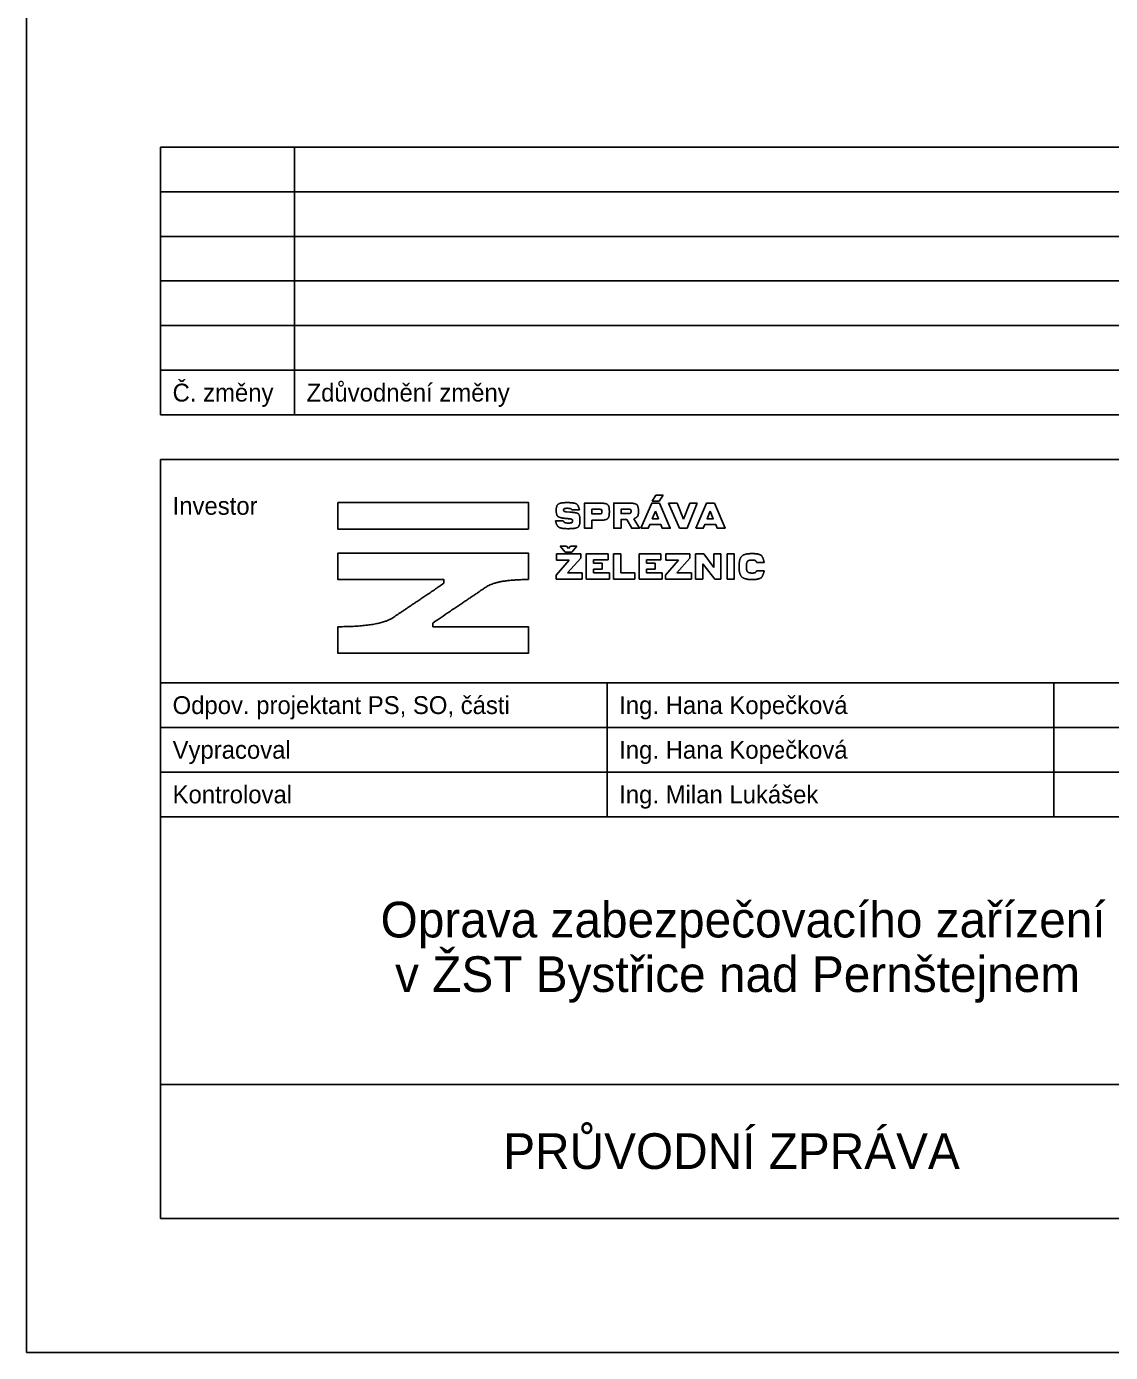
# Model space of a CAD drawing. Extents: x -790471 to -790261, y -984072 to -983775.
# Drawn here: x -790470.6 to -790349.2, y -984071.6 to -983923.1 of the extents above; entities that cross this region are included whole.
import ezdxf

# ---------------------------------------------------------------- set-up
doc = ezdxf.new("R2010")
doc.units = 0
for name, color, linetype in [('logo_sprava_zeleznic', 7, 'Continuous'), ('Ramečky', 7, 'Continuous'), ('Rámečky-tisk', 7, 'Continuous'), ('Text', 7, 'Continuous'), ('Text barevný', 7, 'Continuous')]:
    doc.layers.add(name, color=color, linetype=linetype)

msp = doc.modelspace()

# ---------------------------------------------------------------- linework, layer by layer
at = {"layer": 'logo_sprava_zeleznic'}
for p, q in [((-790400.56, -983976.26), (-790400.12, -983975.6)), ((-790400.12, -983975.6), (-790399.3, -983975.6)), ((-790399.3, -983975.6), (-790399.78, -983976.26)), ((-790409.51, -983977.23), (-790408.69, -983977.23)), ((-790399.78, -983976.26), (-790400.56, -983976.26)), ((-790398.7, -983976.48), (-790397.76, -983976.48)), ((-790397.49, -983979.29), (-790398.7, -983976.48)), ((-790397.76, -983976.48), (-790397.05, -983978.28)), ((-790397.05, -983978.28), (-790396.34, -983976.48)), ((-790395.49, -983976.48), (-790396.64, -983979.29)), ((-790396.34, -983976.48), (-790395.49, -983976.48)), ((-790410.51, -983978.45), (-790411.36, -983978.45)), ((-790409.76, -983977.48), (-790410.15, -983977.45)), ((-790396.64, -983979.29), (-790397.49, -983979.29)), ((-790410.29, -983981.96), (-790410.83, -983981.28)), ((-790410.83, -983981.28), (-790410.14, -983981.28)), ((-790410.14, -983981.28), (-790409.91, -983981.56)), ((-790409.91, -983981.56), (-790409.68, -983981.28)), ((-790409.68, -983981.28), (-790408.97, -983981.28)), ((-790408.97, -983981.28), (-790409.53, -983981.96)), ((-790411.3, -983984.53), (-790409.84, -983982.86)), ((-790411.26, -983982.17), (-790408.55, -983982.17)), ((-790411.26, -983982.86), (-790411.26, -983982.17)), ((-790409.84, -983982.86), (-790411.26, -983982.86)), ((-790409.53, -983981.96), (-790410.29, -983981.96)), ((-790408.55, -983982.63), (-790410.02, -983984.29)), ((-790408.55, -983982.17), (-790408.55, -983982.63)), ((-790407.92, -983982.17), (-790405.49, -983982.17)), ((-790407.92, -983984.99), (-790407.92, -983982.17)), ((-790405.49, -983982.83), (-790407.1, -983982.83)), ((-790407.1, -983982.83), (-790407.1, -983983.2)), ((-790407.1, -983983.2), (-790406.14, -983983.2)), ((-790406.14, -983983.2), (-790406.14, -983983.87)), ((-790405.49, -983982.17), (-790405.49, -983982.83)), ((-790404.86, -983982.17), (-790404.05, -983982.17)), ((-790404.86, -983984.99), (-790404.86, -983982.17)), ((-790404.05, -983982.17), (-790404.05, -983984.28)), ((-790401.99, -983982.17), (-790399.57, -983982.17)), ((-790401.99, -983984.99), (-790401.99, -983982.17)), ((-790399.57, -983982.83), (-790401.18, -983982.83)), ((-790401.18, -983982.83), (-790401.18, -983983.2)), ((-790401.18, -983983.2), (-790400.22, -983983.2)), ((-790400.22, -983983.2), (-790400.22, -983983.87)), ((-790399.57, -983982.17), (-790399.57, -983982.83)), ((-790399.07, -983984.53), (-790397.61, -983982.86)), ((-790399.03, -983982.17), (-790396.33, -983982.17)), ((-790399.03, -983982.86), (-790399.03, -983982.17)), ((-790397.61, -983982.86), (-790399.03, -983982.86)), ((-790396.33, -983982.63), (-790397.8, -983984.29)), ((-790396.33, -983982.17), (-790396.33, -983982.63)), ((-790395.69, -983982.17), (-790394.78, -983982.17)), ((-790395.69, -983984.99), (-790395.69, -983982.17)), ((-790393.53, -983984.99), (-790394.89, -983983.26)), ((-790394.89, -983983.26), (-790394.89, -983984.99)), ((-790394.78, -983982.17), (-790393.63, -983983.68)), ((-790393.63, -983983.68), (-790393.63, -983982.17)), ((-790393.63, -983982.17), (-790392.85, -983982.17)), ((-790392.85, -983982.17), (-790392.85, -983984.99)), ((-790388.84, -983983.12), (-790388.01, -983983.12)), ((-790411.3, -983984.99), (-790411.3, -983984.53)), ((-790410.02, -983984.29), (-790408.39, -983984.29)), ((-790408.39, -983984.29), (-790408.39, -983984.99)), ((-790406.14, -983983.87), (-790407.1, -983983.87)), ((-790407.1, -983983.87), (-790407.1, -983984.3)), ((-790407.1, -983984.3), (-790405.34, -983984.3)), ((-790405.34, -983984.3), (-790405.34, -983984.99)), ((-790404.05, -983984.28), (-790402.47, -983984.28)), ((-790402.47, -983984.28), (-790402.47, -983984.99)), ((-790400.22, -983983.87), (-790401.18, -983983.87)), ((-790401.18, -983983.87), (-790401.18, -983984.3)), ((-790401.18, -983984.3), (-790399.41, -983984.3)), ((-790399.41, -983984.3), (-790399.41, -983984.99)), ((-790399.07, -983984.99), (-790399.07, -983984.53)), ((-790397.8, -983984.29), (-790396.16, -983984.29)), ((-790396.16, -983984.29), (-790396.16, -983984.99)), ((-790388.01, -983984.05), (-790388.83, -983984.05)), ((-790408.39, -983984.99), (-790411.3, -983984.99)), ((-790405.34, -983984.99), (-790407.92, -983984.99)), ((-790402.47, -983984.99), (-790404.86, -983984.99)), ((-790399.41, -983984.99), (-790401.99, -983984.99)), ((-790396.16, -983984.99), (-790399.07, -983984.99)), ((-790394.89, -983984.99), (-790395.69, -983984.99)), ((-790392.85, -983984.99), (-790393.53, -983984.99))]:
    msp.add_line(p, q, dxfattribs=at)
for points in [[(-790435.73, -983976.4), (-790414.41, -983976.4), (-790414.41, -983979.38), (-790435.73, -983979.38)], [(-790401.8, -983979.29), (-790400.98, -983979.29), (-790400.82, -983978.89), (-790399.57, -983978.89), (-790399.41, -983979.29), (-790398.53, -983979.29), (-790399.73, -983976.48), (-790400.6, -983976.48)], [(-790395.65, -983979.29), (-790394.83, -983979.29), (-790394.66, -983978.89), (-790393.42, -983978.89), (-790393.26, -983979.29), (-790392.38, -983979.29), (-790393.57, -983976.48), (-790394.45, -983976.48)], [(-790400.19, -983977.39), (-790399.85, -983978.23), (-790400.54, -983978.23)], [(-790394.04, -983977.39), (-790393.7, -983978.23), (-790394.39, -983978.23)], [(-790392.16, -983982.17), (-790391.35, -983982.17), (-790391.35, -983984.99), (-790392.16, -983984.99)]]:
    msp.add_lwpolyline(points, close=True, dxfattribs=at)
for points in [[(-790406.38, -983976.48), (-790408.11, -983976.48), (-790408.11, -983979.29), (-790407.3, -983979.29), (-790407.3, -983978.39), (-790406.38, -983978.39)], [(-790406.48, -983977.69), (-790407.3, -983977.69), (-790407.3, -983977.17), (-790406.48, -983977.17)], [(-790403.12, -983976.48), (-790404.84, -983976.48), (-790404.84, -983979.29), (-790404.03, -983979.29), (-790404.03, -983978.31), (-790403.39, -983978.31), (-790402.84, -983979.29), (-790401.98, -983979.29), (-790402.59, -983978.22)], [(-790403.22, -983977.64), (-790404.03, -983977.64), (-790404.03, -983977.16), (-790403.22, -983977.16)], [(-790423.87, -983985.46), (-790423.87, -983985.04), (-790435.73, -983985.04), (-790435.73, -983982.07), (-790414.41, -983982.07), (-790414.41, -983985.04)], [(-790425.1, -983989.91), (-790425.1, -983990.32), (-790414.41, -983990.32), (-790414.41, -983993.3), (-790435.73, -983993.3), (-790435.73, -983990.32), (-790435.71, -983990.32)]]:
    msp.add_lwpolyline(points, dxfattribs=at)
for centre, radius, start, end in [((-790411.9, -983999.14), 21.01, 84.2634, 85.3384), ((-790461.18, -983932.6), 64.69, 304.0901, 305.2133), ((-790124.63, -984426.54), 530.02, 124.292, 124.5333)]:
    msp.add_arc(centre, radius, start, end, dxfattribs=at)
for points in [[(-790410.05, -983976.42), (-790410.77, -983976.42), (-790411.29, -983976.71), (-790411.29, -983977.28)], [(-790411.29, -983977.28), (-790411.29, -983977.83), (-790410.87, -983978.14), (-790410.19, -983978.2)], [(-790410.46, -983977.24), (-790410.46, -983977.12), (-790410.3, -983977.06), (-790410.05, -983977.06)], [(-790410.15, -983977.45), (-790410.35, -983977.43), (-790410.46, -983977.36), (-790410.46, -983977.24)], [(-790408.69, -983977.23), (-790408.77, -983976.87), (-790409.09, -983976.42), (-790410.05, -983976.42)], [(-790410.05, -983977.06), (-790409.73, -983977.06), (-790409.55, -983977.17), (-790409.51, -983977.23)], [(-790406.48, -983977.17), (-790406.27, -983977.17), (-790406.17, -983977.26), (-790406.17, -983977.43)], [(-790405.34, -983977.43), (-790405.34, -983976.8), (-790405.73, -983976.48), (-790406.38, -983976.48)], [(-790403.22, -983977.16), (-790403.02, -983977.16), (-790402.91, -983977.23), (-790402.91, -983977.4)], [(-790402.08, -983977.4), (-790402.08, -983976.79), (-790402.49, -983976.48), (-790403.12, -983976.48)], [(-790411.36, -983978.45), (-790411.29, -983978.84), (-790410.93, -983979.34), (-790409.92, -983979.34)], [(-790409.92, -983978.71), (-790410.28, -983978.71), (-790410.46, -983978.57), (-790410.51, -983978.45)], [(-790409.92, -983979.34), (-790409.08, -983979.34), (-790408.63, -983979), (-790408.63, -983978.4)], [(-790409.47, -983978.46), (-790409.47, -983978.61), (-790409.6, -983978.71), (-790409.92, -983978.71)], [(-790409.8, -983978.23), (-790409.6, -983978.26), (-790409.47, -983978.31), (-790409.47, -983978.46)], [(-790408.63, -983978.4), (-790408.63, -983977.79), (-790409.03, -983977.53), (-790409.76, -983977.48)], [(-790406.17, -983977.43), (-790406.17, -983977.59), (-790406.27, -983977.69), (-790406.48, -983977.69)], [(-790406.38, -983978.39), (-790405.73, -983978.39), (-790405.34, -983978.06), (-790405.34, -983977.43)], [(-790402.91, -983977.4), (-790402.91, -983977.55), (-790403.02, -983977.64), (-790403.22, -983977.64)], [(-790402.59, -983978.22), (-790402.27, -983978.08), (-790402.08, -983977.8), (-790402.08, -983977.4)], [(-790389.36, -983982.13), (-790390.22, -983982.13), (-790390.82, -983982.73), (-790390.82, -983983.58)], [(-790390, -983983.58), (-790390, -983983.18), (-790389.76, -983982.85), (-790389.36, -983982.85)], [(-790388.01, -983983.12), (-790388.06, -983982.8), (-790388.4, -983982.13), (-790389.36, -983982.13)], [(-790389.36, -983982.85), (-790389.02, -983982.85), (-790388.88, -983983.05), (-790388.84, -983983.12)], [(-790390.82, -983983.58), (-790390.82, -983984.43), (-790390.22, -983985.04), (-790389.36, -983985.04)], [(-790389.36, -983984.31), (-790389.76, -983984.31), (-790390, -983983.99), (-790390, -983983.58)], [(-790389.36, -983985.04), (-790388.37, -983985.04), (-790388.05, -983984.31), (-790388.01, -983984.05)], [(-790388.83, -983984.05), (-790388.87, -983984.12), (-790389.02, -983984.31), (-790389.36, -983984.31)], [(-790435.71, -983990.32), (-790431.06, -983990.31), (-790428.08, -983988.3), (-790424.92, -983986.18)], [(-790414.41, -983985.04), (-790417.9, -983985.04), (-790420.38, -983986.71), (-790423.25, -983988.65)]]:
    msp.add_open_spline(points, degree=2, dxfattribs=at)
at = {"layer": 'Ramečky'}
for p, q in [((-790275.59, -983936.6), (-790455.59, -983936.6)), ((-790455.59, -983936.6), (-790455.59, -983966.6)), ((-790440.59, -983936.6), (-790440.59, -983966.6)), ((-790305.59, -983941.6), (-790455.59, -983941.6)), ((-790305.59, -983946.6), (-790455.59, -983946.6)), ((-790305.59, -983951.6), (-790455.59, -983951.6)), ((-790305.59, -983956.6), (-790455.59, -983956.6)), ((-790305.59, -983961.6), (-790455.59, -983961.6)), ((-790275.59, -983966.6), (-790455.59, -983966.6)), ((-790275.59, -983971.6), (-790455.59, -983971.6)), ((-790455.59, -984056.6), (-790455.59, -983971.6)), ((-790455.59, -983996.6), (-790325.59, -983996.6)), ((-790455.59, -984001.6), (-790325.59, -984001.6)), ((-790455.59, -984006.6), (-790325.59, -984006.6)), ((-790455.59, -984011.6), (-790325.59, -984011.6)), ((-790455.59, -984041.6), (-790275.59, -984041.6)), ((-790455.59, -984056.6), (-790275.59, -984056.6))]:
    msp.add_line(p, q, dxfattribs=at)
for points in [[(-790405.59, -983996.6), (-790405.59, -984011.6)], [(-790355.59, -983996.6), (-790355.59, -984011.6)]]:
    msp.add_lwpolyline(points, dxfattribs=at)
at = {"layer": 'Rámečky-tisk'}
msp.add_line((-790470.59, -983774.6), (-790470.59, -984071.6), dxfattribs=at)
msp.add_lwpolyline([(-790470.59, -984071.6), (-790260.59, -984071.6), (-790260.59, -983774.6)], dxfattribs=at)

# ---------------------------------------------------------------- texts
at = {"layer": 'Text'}
for s, p in [('Č. změny', (-790454.24, -983965.1)), ('Zdůvodnění změny', (-790439.24, -983965.1)), ('Investor', (-790454.24, -983977.78)), ('Odpov. projektant PS, SO, části', (-790454.24, -984000.1)), ('Ing. Hana Kopečková', (-790404.24, -984000.1)), ('Vypracoval', (-790454.24, -984005.1)), ('Ing. Hana Kopečková', (-790404.24, -984005.1)), ('Kontroloval', (-790454.24, -984010.1)), ('Ing. Milan Lukášek', (-790404.24, -984010.1))]:
    msp.add_text(s, height=2, dxfattribs=at).set_placement(p)
at = {"layer": 'Text barevný'}
for s, p in [('Oprava zabezpečovacího zařízení', (-790430.95, -984025.12)), ('v ŽST Bystřice nad Pernštejnem', (-790429.33, -984031.23)), ('PRŮVODNÍ ZPRÁVA', (-790417.22, -984051.05))]:
    msp.add_text(s, height=4, dxfattribs=at).set_placement(p)

doc.saveas('drawing.dxf')
